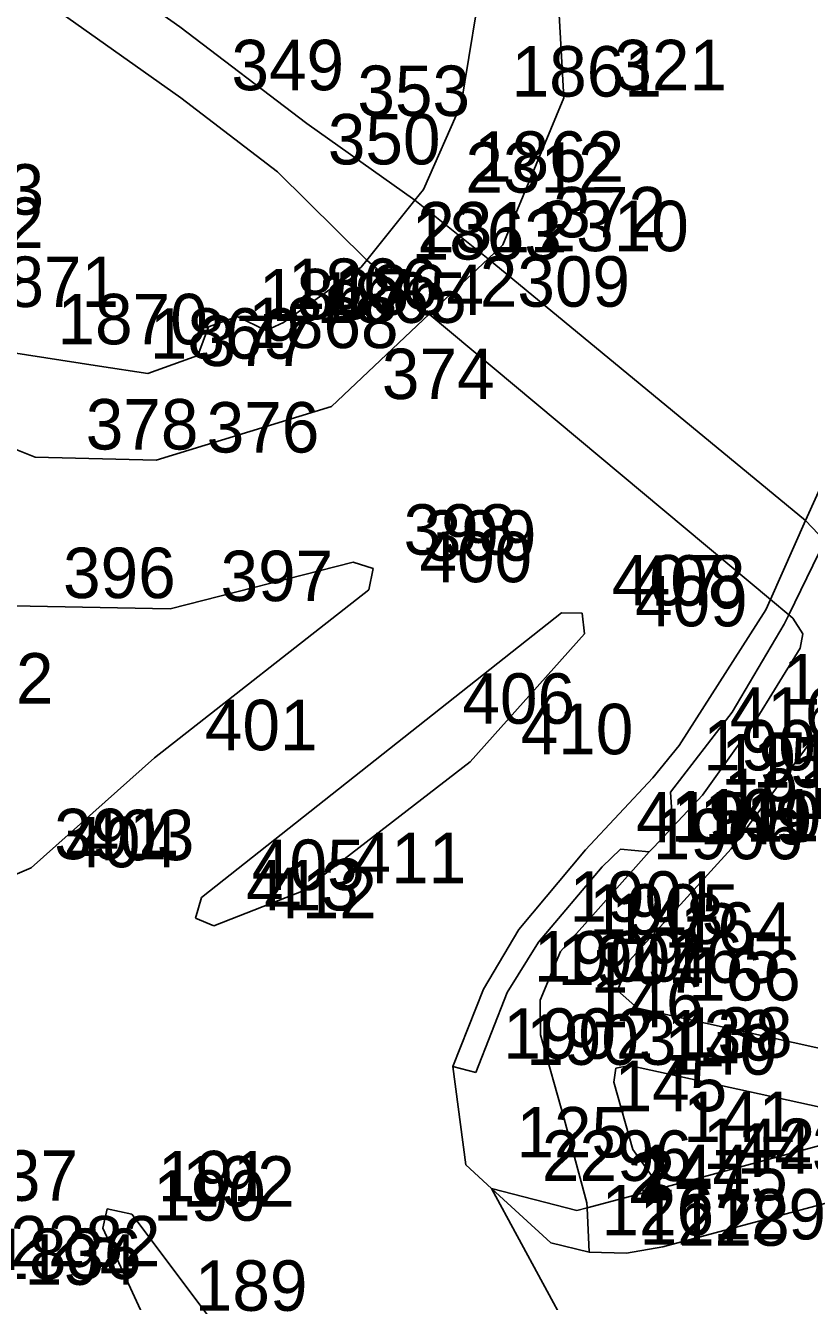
# Model space of a CAD drawing. Extents: x -822293 to -820259, y -1071573 to -1068794.
# Drawn here: x -821367.5 to -821336.5, y -1070340.8 to -1070290.2 of the extents above; entities that cross this region are included whole.
import ezdxf

# ---------------------------------------------------------------- set-up
doc = ezdxf.new("R2010")
doc.units = 0
for name, color, linetype in [('Vrstva 2', 7, 'Continuous'), ('Vrstva 3', 7, 'Continuous'), ('Vrstva 8', 7, 'Continuous'), ('Vrstva 9', 7, 'Continuous')]:
    doc.layers.add(name, color=color, linetype=linetype)

msp = doc.modelspace()

# ---------------------------------------------------------------- linework, layer by layer
at = {"layer": 'Vrstva 2'}
for p, q in [((-821334.24, -1070334.1), (-821341.37, -1070336.02)), ((-821341.37, -1070336.02), (-821345.3, -1070337.07)), ((-821345.7, -1070337.18), (-821349.09, -1070336.3)), ((-821341.99, -1070349.38), (-821349.09, -1070336.3)), ((-821345.3, -1070337.07), (-821345.7, -1070337.18))]:
    msp.add_line(p, q, dxfattribs=at)
at = {"layer": 'Vrstva 3'}
for p, q in [((-821361.43, -1070290.25), (-821373.25, -1070281.92)), ((-821346.81, -1070282.86), (-821346.22, -1070293.07)), ((-821374.94, -1070283.47), (-821361.39, -1070293.07)), ((-821350.29, -1070293.32), (-821349.68, -1070289.62)), ((-821356.4, -1070294.09), (-821361.43, -1070290.25)), ((-821361.39, -1070293.07), (-821357.57, -1070296.01)), ((-821346.22, -1070293.07), (-821348.64, -1070298.9)), ((-821351.78, -1070296.7), (-821350.29, -1070293.32)), ((-821352.12, -1070297.13), (-821356.4, -1070294.09)), ((-821357.57, -1070296.01), (-821354.03, -1070299.5)), ((-821352.12, -1070297.13), (-821351.78, -1070296.7)), ((-821354.03, -1070299.5), (-821352.12, -1070297.13)), ((-821352.12, -1070297.13), (-821349.22, -1070299.45)), ((-821348.64, -1070298.9), (-821349.22, -1070299.45)), ((-821357.33, -1070301.98), (-821354.25, -1070299.78)), ((-821354.25, -1070299.78), (-821354.03, -1070299.5)), ((-821354.03, -1070299.5), (-821351.55, -1070301.65)), ((-821349.22, -1070299.45), (-821351.55, -1070301.65)), ((-821349.22, -1070299.45), (-821336.65, -1070309.83)), ((-821360.3, -1070302.15), (-821359.16, -1070301.74)), ((-821359.16, -1070301.74), (-821358.02, -1070302.29)), ((-821351.55, -1070301.65), (-821355.43, -1070305.31)), ((-821351.55, -1070301.65), (-821338.04, -1070312.95)), ((-821360.72, -1070303.29), (-821360.3, -1070302.15)), ((-821358.02, -1070302.29), (-821357.33, -1070301.98)), ((-821368.28, -1070303.14), (-821364.62, -1070303.71)), ((-821362.7, -1070304), (-821360.72, -1070303.29)), ((-821364.62, -1070303.71), (-821362.7, -1070304)), ((-821367.16, -1070307.31), (-821374.57, -1070304.4)), ((-821355.43, -1070305.31), (-821362.37, -1070307.43)), ((-821362.37, -1070307.43), (-821367.16, -1070307.31)), ((-821336.65, -1070309.83), (-821335.69, -1070307.7)), ((-821338.04, -1070312.95), (-821336.65, -1070309.83)), ((-821336.65, -1070309.83), (-821335.88, -1070310.63)), ((-821337.31, -1070313.56), (-821335.88, -1070310.63)), ((-821354.57, -1070311.48), (-821361.82, -1070313.32)), ((-821353.77, -1070311.72), (-821354.57, -1070311.48)), ((-821353.94, -1070312.57), (-821353.77, -1070311.72)), ((-821362.44, -1070319.23), (-821353.94, -1070312.57)), ((-821338.22, -1070313.36), (-821338.04, -1070312.95)), ((-821338.04, -1070312.95), (-821337.31, -1070313.56)), ((-821361.82, -1070313.32), (-821368.06, -1070313.2)), ((-821346.32, -1070313.49), (-821352.24, -1070318.18)), ((-821345.49, -1070313.5), (-821346.32, -1070313.49)), ((-821345.4, -1070314.32), (-821345.49, -1070313.5)), ((-821341.65, -1070318.74), (-821338.22, -1070313.36)), ((-821339.55, -1070317.42), (-821337.49, -1070313.93)), ((-821337.49, -1070313.93), (-821337.31, -1070313.56)), ((-821337.31, -1070313.56), (-821337.15, -1070313.7)), ((-821337.15, -1070313.7), (-821336.75, -1070314.31)), ((-821349.93, -1070319.39), (-821345.4, -1070314.32)), ((-821336.75, -1070314.31), (-821336.86, -1070314.88)), ((-821336.86, -1070314.88), (-821338.68, -1070317.85)), ((-821341.99, -1070320.59), (-821339.55, -1070317.42)), ((-821340.73, -1070320.71), (-821338.68, -1070317.85)), ((-821352.24, -1070318.18), (-821360.58, -1070324.77)), ((-821336.34, -1070318.47), (-821339.59, -1070322.84)), ((-821342.7, -1070320.03), (-821341.65, -1070318.74)), ((-821367.32, -1070323.59), (-821362.44, -1070319.23)), ((-821356.55, -1070324.5), (-821349.93, -1070319.39)), ((-821345.36, -1070322.88), (-821342.7, -1070320.03)), ((-821341.9, -1070321.96), (-821341.99, -1070320.59)), ((-821341.9, -1070321.96), (-821340.73, -1070320.71)), ((-821342.66, -1070322.77), (-821341.9, -1070321.96)), ((-821348, -1070326.03), (-821345.36, -1070322.88)), ((-821346.35, -1070326.91), (-821342.84, -1070322.96)), ((-821344.7, -1070323.55), (-821343.98, -1070322.85)), ((-821343.98, -1070322.85), (-821342.84, -1070322.96)), ((-821339.59, -1070322.84), (-821343.62, -1070327.26)), ((-821342.84, -1070322.96), (-821342.66, -1070322.77)), ((-821367.97, -1070323.87), (-821367.32, -1070323.59)), ((-821347.22, -1070326.54), (-821344.7, -1070323.55)), ((-821360.09, -1070325.89), (-821356.55, -1070324.5)), ((-821360.58, -1070324.77), (-821360.81, -1070325.58)), ((-821360.81, -1070325.58), (-821360.09, -1070325.89)), ((-821349.41, -1070328.4), (-821348, -1070326.03)), ((-821348.47, -1070328.53), (-821347.22, -1070326.54)), ((-821347.16, -1070328.84), (-821346.35, -1070326.91)), ((-821343.62, -1070327.26), (-821344.1, -1070328.45)), ((-821350.62, -1070331.46), (-821349.41, -1070328.4)), ((-821349.71, -1070331.7), (-821348.47, -1070328.53)), ((-821344.1, -1070328.45), (-821343.3, -1070329.15)), ((-821347.15, -1070330.21), (-821347.16, -1070328.84)), ((-821343.3, -1070329.15), (-821333.35, -1070331.36)), ((-821346.21, -1070333.54), (-821347.15, -1070330.21)), ((-821350.62, -1070331.46), (-821349.71, -1070331.7)), ((-821350.1, -1070335.37), (-821350.62, -1070331.46)), ((-821344.16, -1070331.53), (-821344.24, -1070332.09)), ((-821343.62, -1070331.42), (-821344.16, -1070331.53)), ((-821334.28, -1070333.47), (-821343.62, -1070331.42)), ((-821344.24, -1070332.09), (-821343.49, -1070334.76)), ((-821345.31, -1070336.87), (-821346.21, -1070333.54)), ((-821342.3, -1070338.62), (-821323.1, -1070333.47)), ((-821343.49, -1070334.76), (-821342.72, -1070335.83)), ((-821350.1, -1070335.37), (-821349.09, -1070336.3)), ((-821342.72, -1070335.83), (-821341.37, -1070336.02)), ((-821349.09, -1070336.3), (-821346.73, -1070338.46)), ((-821364.31, -1070337.11), (-821364.49, -1070337.88)), ((-821363.34, -1070337.32), (-821364.31, -1070337.11)), ((-821345.3, -1070337.07), (-821345.31, -1070336.87)), ((-821345.22, -1070338.83), (-821345.3, -1070337.07)), ((-821358.17, -1070344.19), (-821363.34, -1070337.32)), ((-821364.49, -1070337.88), (-821362.84, -1070341.45)), ((-821346.73, -1070338.46), (-821345.22, -1070338.83)), ((-821343.74, -1070338.87), (-821342.3, -1070338.62)), ((-821345.22, -1070338.83), (-821343.74, -1070338.87))]:
    msp.add_line(p, q, dxfattribs=at)
at = {"layer": 'Vrstva 8'}
for p, q in [((-821361.43, -1070290.25), (-821361.43, -1070290.25)), ((-821361.39, -1070293.07), (-821361.39, -1070293.07)), ((-821346.22, -1070293.07), (-821346.22, -1070293.07)), ((-821350.29, -1070293.32), (-821350.29, -1070293.32)), ((-821356.4, -1070294.09), (-821356.4, -1070294.09)), ((-821357.57, -1070296.01), (-821357.57, -1070296.01)), ((-821351.78, -1070296.7), (-821351.78, -1070296.7)), ((-821352.12, -1070297.13), (-821352.12, -1070297.13)), ((-821348.64, -1070298.9), (-821348.64, -1070298.9)), ((-821354.25, -1070299.78), (-821354.25, -1070299.78)), ((-821354.03, -1070299.5), (-821354.03, -1070299.5)), ((-821349.22, -1070299.45), (-821349.22, -1070299.45)), ((-821359.16, -1070301.74), (-821359.16, -1070301.74)), ((-821351.55, -1070301.65), (-821351.55, -1070301.65)), ((-821360.3, -1070302.15), (-821360.3, -1070302.15)), ((-821358.02, -1070302.29), (-821358.02, -1070302.29)), ((-821357.33, -1070301.98), (-821357.33, -1070301.98)), ((-821360.72, -1070303.29), (-821360.72, -1070303.29)), ((-821364.62, -1070303.71), (-821364.62, -1070303.71)), ((-821362.7, -1070304), (-821362.7, -1070304)), ((-821355.43, -1070305.31), (-821355.43, -1070305.31)), ((-821367.16, -1070307.31), (-821367.16, -1070307.31)), ((-821362.37, -1070307.43), (-821362.37, -1070307.43)), ((-821336.65, -1070309.83), (-821336.65, -1070309.83)), ((-821354.57, -1070311.48), (-821354.57, -1070311.48)), ((-821353.77, -1070311.72), (-821353.77, -1070311.72)), ((-821353.94, -1070312.57), (-821353.94, -1070312.57)), ((-821338.04, -1070312.95), (-821338.04, -1070312.95)), ((-821361.82, -1070313.32), (-821361.82, -1070313.32)), ((-821346.32, -1070313.49), (-821346.32, -1070313.49)), ((-821345.49, -1070313.5), (-821345.49, -1070313.5)), ((-821338.22, -1070313.36), (-821338.22, -1070313.36)), ((-821337.49, -1070313.93), (-821337.49, -1070313.93)), ((-821337.31, -1070313.56), (-821337.31, -1070313.56)), ((-821337.15, -1070313.7), (-821337.15, -1070313.7)), ((-821345.4, -1070314.32), (-821345.4, -1070314.32)), ((-821336.75, -1070314.31), (-821336.75, -1070314.31)), ((-821336.86, -1070314.88), (-821336.86, -1070314.88)), ((-821339.55, -1070317.42), (-821339.55, -1070317.42)), ((-821338.68, -1070317.85), (-821338.68, -1070317.85)), ((-821352.24, -1070318.18), (-821352.24, -1070318.18)), ((-821341.65, -1070318.74), (-821341.65, -1070318.74)), ((-821362.44, -1070319.23), (-821362.44, -1070319.23)), ((-821349.93, -1070319.39), (-821349.93, -1070319.39)), ((-821342.7, -1070320.03), (-821342.7, -1070320.03)), ((-821341.99, -1070320.59), (-821341.99, -1070320.59)), ((-821340.73, -1070320.71), (-821340.73, -1070320.71)), ((-821341.9, -1070321.96), (-821341.9, -1070321.96)), ((-821345.36, -1070322.88), (-821345.36, -1070322.88)), ((-821343.98, -1070322.85), (-821343.98, -1070322.85)), ((-821342.84, -1070322.96), (-821342.84, -1070322.96)), ((-821342.66, -1070322.77), (-821342.66, -1070322.77)), ((-821339.59, -1070322.84), (-821339.59, -1070322.84)), ((-821367.32, -1070323.59), (-821367.32, -1070323.59)), ((-821344.7, -1070323.55), (-821344.7, -1070323.55)), ((-821356.55, -1070324.5), (-821356.55, -1070324.5)), ((-821360.58, -1070324.77), (-821360.58, -1070324.77)), ((-821360.81, -1070325.58), (-821360.81, -1070325.58)), ((-821360.09, -1070325.89), (-821360.09, -1070325.89)), ((-821348, -1070326.03), (-821348, -1070326.03)), ((-821347.22, -1070326.54), (-821347.22, -1070326.54)), ((-821346.35, -1070326.91), (-821346.35, -1070326.91)), ((-821343.62, -1070327.26), (-821343.62, -1070327.26)), ((-821349.41, -1070328.4), (-821349.41, -1070328.4)), ((-821348.47, -1070328.53), (-821348.47, -1070328.53)), ((-821344.1, -1070328.45), (-821344.1, -1070328.45)), ((-821347.16, -1070328.84), (-821347.16, -1070328.84)), ((-821343.3, -1070329.15), (-821343.3, -1070329.15)), ((-821347.15, -1070330.21), (-821347.15, -1070330.21)), ((-821350.62, -1070331.46), (-821350.62, -1070331.46)), ((-821349.71, -1070331.7), (-821349.71, -1070331.7)), ((-821344.16, -1070331.53), (-821344.16, -1070331.53)), ((-821343.62, -1070331.42), (-821343.62, -1070331.42)), ((-821344.24, -1070332.09), (-821344.24, -1070332.09)), ((-821346.21, -1070333.54), (-821346.21, -1070333.54)), ((-821343.49, -1070334.76), (-821343.49, -1070334.76)), ((-821350.1, -1070335.37), (-821350.1, -1070335.37)), ((-821342.72, -1070335.83), (-821342.72, -1070335.83)), ((-821341.37, -1070336.02), (-821341.37, -1070336.02)), ((-821349.09, -1070336.3), (-821349.09, -1070336.3)), ((-821364.31, -1070337.11), (-821364.31, -1070337.11)), ((-821345.7, -1070337.18), (-821345.7, -1070337.18)), ((-821345.31, -1070336.87), (-821345.31, -1070336.87)), ((-821345.3, -1070337.07), (-821345.3, -1070337.07)), ((-821363.34, -1070337.32), (-821363.34, -1070337.32)), ((-821364.49, -1070337.88), (-821364.49, -1070337.88)), ((-821346.73, -1070338.46), (-821346.73, -1070338.46)), ((-821342.3, -1070338.62), (-821342.3, -1070338.62)), ((-821345.22, -1070338.83), (-821345.22, -1070338.83)), ((-821343.74, -1070338.87), (-821343.74, -1070338.87))]:
    msp.add_line(p, q, dxfattribs=at)

# ---------------------------------------------------------------- texts
at = {"layer": 'Vrstva 9'}
for s, p in [('349', (-821359.39, -1070292.77)), ('321', (-821344.22, -1070292.77)), ('1861', (-821348.29, -1070293.02)), ('353', (-821354.4, -1070293.79)), ('350', (-821355.57, -1070295.71)), ('2312', (-821350.12, -1070296.83)), ('1862', (-821349.78, -1070296.4)), ('1873', (-821372.76, -1070297.7)), ('372', (-821346.64, -1070298.6)), ('1872', (-821372.77, -1070299.02)), ('2311', (-821352.03, -1070299.2)), ('2310', (-821347.22, -1070299.15)), ('1863', (-821352.25, -1070299.48)), ('1871', (-821369.79, -1070301.36)), ('2309', (-821349.55, -1070301.35)), ('1867', (-821358.3, -1070301.85)), ('1866', (-821357.16, -1070301.44)), ('1864', (-821355.33, -1070301.68)), ('1865', (-821356.02, -1070301.99)), ('1870', (-821366.28, -1070302.84)), ('1869', (-821362.62, -1070303.41)), ('1868', (-821358.72, -1070302.99)), ('377', (-821360.7, -1070303.7)), ('374', (-821353.43, -1070305.01)), ('378', (-821365.16, -1070307.01)), ('376', (-821360.37, -1070307.13)), ('398', (-821352.57, -1070311.18)), ('399', (-821351.77, -1070311.42)), ('400', (-821351.94, -1070312.27)), ('396', (-821366.06, -1070312.9)), ('397', (-821359.82, -1070313.02)), ('407', (-821344.32, -1070313.19)), ('408', (-821343.49, -1070313.2)), ('409', (-821343.4, -1070314.02)), ('392', (-821370.9, -1070317.08)), ('1907', (-821337.55, -1070317.12)), ('406', (-821350.24, -1070317.88)), ('416', (-821339.65, -1070318.44)), ('401', (-821360.44, -1070318.93)), ('410', (-821347.93, -1070319.09)), ('1900', (-821340.7, -1070319.73)), ('1913', (-821339.99, -1070320.29)), ('150', (-821338.73, -1070320.41)), ('1912', (-821339.9, -1070321.66)), ('415', (-821343.36, -1070322.58)), ('1910', (-821341.98, -1070322.55)), ('1911', (-821340.66, -1070322.47)), ('163', (-821337.59, -1070322.54)), ('149', (-821340.84, -1070322.66)), ('391', (-821366.41, -1070323.25)), ('404', (-821365.97, -1070323.57)), ('403', (-821365.32, -1070323.29)), ('1906', (-821342.7, -1070323.25)), ('405', (-821358.58, -1070324.47)), ('411', (-821354.55, -1070324.2)), ('413', (-821358.81, -1070325.28)), ('412', (-821358.09, -1070325.59)), ('1901', (-821346, -1070325.73)), ('1905', (-821345.22, -1070326.24)), ('148', (-821344.35, -1070326.61)), ('164', (-821341.62, -1070326.96)), ('1909', (-821347.41, -1070328.1)), ('165', (-821342.1, -1070328.15)), ('1904', (-821346.47, -1070328.23)), ('147', (-821345.16, -1070328.54)), ('166', (-821341.3, -1070328.85)), ('146', (-821345.15, -1070329.91)), ('1902', (-821348.62, -1070331.16)), ('138', (-821341.62, -1070331.12)), ('1903', (-821347.71, -1070331.4)), ('139', (-821342.16, -1070331.23)), ('140', (-821342.24, -1070331.79)), ('145', (-821344.21, -1070333.24)), ('141', (-821341.49, -1070334.46)), ('125', (-821348.1, -1070335.07)), ('142', (-821340.72, -1070335.53)), ('143', (-821339.37, -1070335.72)), ('2296', (-821347.09, -1070336)), ('1837', (-821371.42, -1070336.79)), ('2475', (-821343.3, -1070336.77)), ('144', (-821343.31, -1070336.57)), ('191', (-821362.31, -1070336.81)), ('192', (-821361.34, -1070337.02)), ('2', (-821343.7, -1070336.88)), ('190', (-821362.49, -1070337.58)), ('126', (-821344.73, -1070338.16)), ('127', (-821343.22, -1070338.53)), ('128', (-821341.74, -1070338.57)), ('129', (-821340.3, -1070338.32)), ('2282', (-821368.15, -1070339.39)), ('1836', (-821368.9, -1070339.89)), ('194', (-821367.58, -1070340.12)), ('189', (-821360.84, -1070341.15))]:
    msp.add_text(s, height=2, dxfattribs=at).set_placement(p)

doc.saveas('drawing.dxf')
